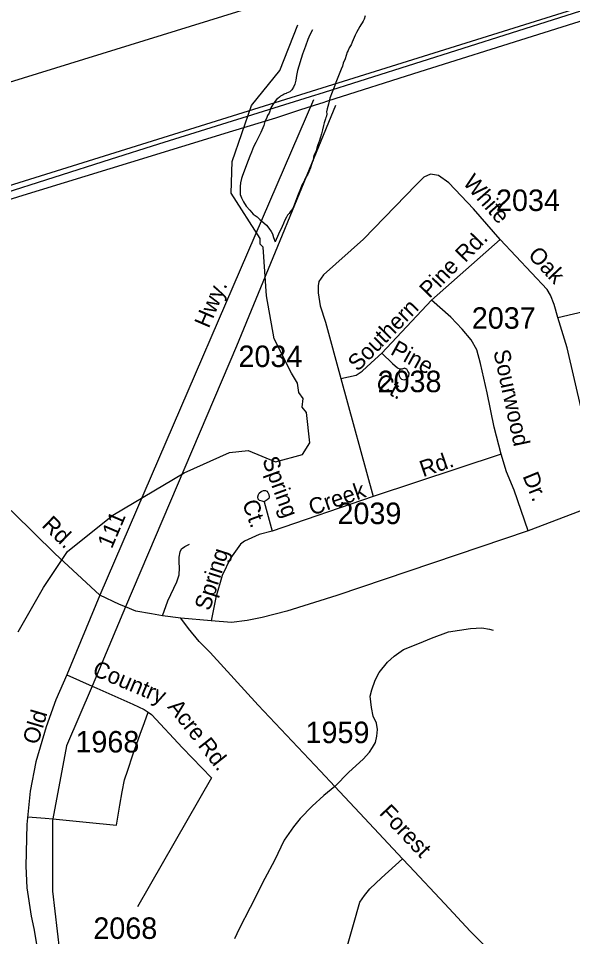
# Model space of a CAD drawing. Extents: x 2260773 to 2342389, y 552869 to 618546.
# Drawn here: x 2313503 to 2316729, y 575994 to 581334 of the extents above; entities that cross this region are included whole.
import ezdxf

# ---------------------------------------------------------------- set-up
doc = ezdxf.new("R2010")
doc.units = 0
for name, color, linetype in [('Exist Aviation Commercial or Municipal Perimeter Paved', 7, 'Continuous'), ('Exist Boundary Land Use Reservation Military US Department of Defense', 7, 'Continuous'), ('Exist Boundary Political City Limit New', 7, 'Continuous'), ('Exist Boundary Political Urban Extension UEB', 7, 'Continuous'), ('Exist Hydrographic Misc Water Feature', 7, 'Continuous'), ('Exist Road Non-System Type 51', 7, 'Continuous'), ('Exist Road Non-System Type 51 Label', 7, 'Continuous'), ('Exist Road Secondary Type 51 Attributed', 7, 'Continuous'), ('Exist Road Secondary Type 51 Label', 7, 'Continuous'), ('Exist Road Secondary Type 51 Number Label', 7, 'Continuous'), ('Map Preparation Boundary City Limit Buffer Line', 7, 'Continuous')]:
    doc.layers.add(name, color=color, linetype=linetype)

msp = doc.modelspace()

# ---------------------------------------------------------------- linework, layer by layer
at = {"layer": 'Exist Aviation Commercial or Municipal Perimeter Paved'}
msp.add_lwpolyline([(2316391.2, 581871.9), (2313259.5, 580902.9), (2308808.6, 579533.6), (2306700.6, 578883.4), (2306637, 578862.6), (2306607.1, 578850.4)], dxfattribs=at)
at = {"layer": 'Exist Boundary Land Use Reservation Military US Department of Defense'}
msp.add_line((2317609.8, 581659), (2311535.5, 579763.7), dxfattribs=at)
at = {"layer": 'Exist Boundary Political City Limit New'}
for points in [[(2317147.2, 581434.1), (2315839.8, 581022.8), (2315302, 580851.4), (2315268.5, 580840.8), (2315261.8, 580838.6), (2315139.2, 580800.2), (2315046.5, 580769.4), (2315000, 580753.9)], [(2315000, 580753.9), (2314749.5, 580677.9), (2314155.2, 580496.1), (2313504.5, 580295.5), (2313282, 580226.7)]]:
    msp.add_lwpolyline(points, dxfattribs=at)
at = {"layer": 'Exist Boundary Political Urban Extension UEB'}
msp.add_line((2314127.2, 577910.7), (2313932, 577451), dxfattribs=at)
for points in [[(2315348.4, 580828), (2314772, 579428.4), (2314127.2, 577910.7)], [(2313932, 577451), (2313784, 577102.6), (2313703.2, 576678.7)], [(2313703.2, 576678.7), (2313701.6, 576670.4), (2313701.6, 576258.8), (2313742.8, 575908.9), (2313886.9, 575517.8), (2314133.9, 575167.9), (2314689.7, 574612.2), (2315604, 573728.1)]]:
    msp.add_lwpolyline(points, dxfattribs=at)
at = {"layer": 'Exist Hydrographic Misc Water Feature'}
for points in [[(2315521.3, 581348.9), (2315515.6, 581328.7), (2315509.2, 581316.7), (2315503.7, 581308.6), (2315495.7, 581296.8), (2315489.8, 581286.7), (2315479.9, 581268.4), (2315470.1, 581252.4), (2315462.3, 581236.1), (2315450.8, 581208.2), (2315445, 581196.1), (2315438.9, 581180), (2315427.4, 581161.9), (2315421.7, 581147.7), (2315417.4, 581137.9), (2315404, 581097.7), (2315394, 581073.7), (2315388.5, 581055.4), (2315380.9, 581037.5), (2315357.5, 580979.4), (2315351.5, 580961.3), (2315347.6, 580953.3), (2315343.8, 580943), (2315329.8, 580904.9), (2315316.5, 580868.8), (2315307, 580834.9), (2315299.5, 580806.8), (2315297.2, 580790.6), (2315297.8, 580778.8), (2315296, 580764.8), (2315292.1, 580756.9), (2315289.8, 580748.7), (2315281.8, 580726.8), (2315278.3, 580710.7), (2315272.6, 580686.4), (2315266.9, 580662.5), (2315261.1, 580642.3), (2315253.3, 580618.4), (2315251.3, 580614.2), (2315245.7, 580598.4), (2315243.3, 580592.3), (2315235.7, 580564.2), (2315231.8, 580556.3), (2315227.9, 580548), (2315224, 580540), (2315220.5, 580526), (2315218.7, 580510), (2315212.5, 580495.9), (2315208.8, 580483.9), (2315206.8, 580477.7), (2315203.3, 580463.7), (2315187.5, 580427.9), (2315175.6, 580409.5)], [(2313502.2, 577765.9), (2313649.2, 578024.5), (2313789.3, 578233.6), (2314053.4, 578444.4), (2314467.4, 578690.9), (2314732.3, 578809.8), (2314840.4, 578820.8), (2314999.3, 578755), (2315157.4, 578797.5), (2315198.4, 578864.8), (2315179.3, 579041.2), (2315154.3, 579073), (2315161.3, 579122.5), (2315136.2, 579157.6), (2315127.2, 579213), (2315093.2, 579270.8), (2314991.3, 579470.1), (2314947.2, 579721), (2314927.3, 580002.4), (2314910.3, 580021.3), (2314910.3, 580054.2), (2314741.3, 580316.4), (2314747.3, 580500.5), (2314860.2, 580826.6), (2315024.3, 581030.2), (2315130.3, 581296.9)], [(2315214.2, 581267.4), (2315198.6, 581237.3), (2315187.1, 581211.5), (2315173.4, 581173), (2315155.7, 581124.9), (2315126.8, 581030.8), (2315121.3, 581000.7), (2315117.4, 580974.6), (2315111.8, 580950.7), (2315103.8, 580934.4), (2315094, 580918.5), (2315082.3, 580906.5), (2315064.3, 580898.2), (2315060.6, 580896.4), (2315054.2, 580894), (2315050.5, 580892.2), (2315044.6, 580889.8), (2315036.8, 580885.7), (2315028.4, 580881.7), (2315022.4, 580875.7), (2315012.8, 580867.4), (2315004.6, 580861.4), (2314997, 580851.5), (2314989, 580841.5), (2314983.1, 580833.4), (2314977.5, 580823.3), (2314973.2, 580813.4), (2314961.9, 580783.1), (2314953.5, 580768.9), (2314948, 580751.1), (2314938.2, 580733.1), (2314930.8, 580710.7), (2314914.6, 580670.5), (2314904.9, 580650.5), (2314895.3, 580630.5), (2314885.5, 580612.5), (2314871.7, 580586.2), (2314860.4, 580556.2), (2314850.4, 580532.2), (2314841, 580508.1), (2314808, 580419.8), (2314802, 580401.6), (2314796.3, 580377.7), (2314794.2, 580355.7), (2314793, 580327.5), (2314793, 580309.7), (2314801.2, 580289.8), (2314813.3, 580267.7), (2314829.3, 580242.2), (2314849.6, 580218.5), (2314870.3, 580194.3), (2314892.4, 580178.8), (2314908.2, 580165), (2314930.6, 580145), (2314947, 580131.2), (2314960.5, 580113.4), (2314975.1, 580093.7), (2314981.2, 580079.8), (2314987.8, 580059.8), (2314997.8, 580033.9)], [(2315175.6, 580409.5), (2315169.7, 580397.8), (2315163.5, 580383.7), (2315152.2, 580363.5), (2315144, 580343.2), (2315130.7, 580309.1), (2315121.3, 580285), (2315107.3, 580247), (2315099.5, 580228.7), (2315085.6, 580208.9), (2315079.6, 580198.8), (2315070, 580188.5), (2315064.1, 580178.5), (2315052.2, 580156.3), (2315046.6, 580140.5), (2315038.8, 580124.3), (2315017.1, 580078), (2314997.8, 580033.9)]]:
    msp.add_lwpolyline(points, dxfattribs=at)
at = {"layer": 'Exist Road Non-System Type 51'}
msp.add_line((2314037.6, 580513), (2312481.5, 580018.9), dxfattribs=at)
for points in [[(2317609.8, 581659), (2317591.1, 581637.1), (2317531.5, 581598.5), (2316933.8, 581426.6), (2315245.6, 580891.4), (2315231.8, 580887.1)], [(2315231.8, 580887.1), (2314318, 580602.1), (2314037.6, 580513)], [(2315618.1, 579387.3), (2315681.3, 579325.9), (2315709.2, 579301.8), (2315727.8, 579294.3)], [(2315727.8, 579294.3), (2315719.7, 579286.2), (2315717.8, 579278.3), (2315717.9, 579266.3), (2315718.2, 579254.3), (2315724.3, 579242.4), (2315732.3, 579236.5), (2315748.3, 579232.5), (2315760.4, 579234.8), (2315770.2, 579244.8), (2315776, 579252.9), (2315777.9, 579271), (2315769.8, 579282.8), (2315763.6, 579292.8), (2315757.7, 579294.7), (2315749.6, 579298.6), (2315735.8, 579294.5), (2315727.8, 579294.3)], [(2314933.2, 578522.2), (2314921.1, 578526.1), (2314907.1, 578529.9), (2314899, 578537.8), (2314896.8, 578551.9), (2314900.8, 578563.9), (2314904.6, 578571.9), (2314916.4, 578581.9), (2314930.4, 578588.1), (2314940.4, 578588.3), (2314948.5, 578584.4), (2314954.5, 578576.5), (2314960.7, 578564.5), (2314962.9, 578550.6), (2314960.8, 578542.5), (2314951, 578534.5), (2314945.1, 578530.3), (2314933.2, 578522.2)], [(2314933.2, 578522.2), (2314980.9, 578352.2)], [(2314341.5, 577860), (2314372.7, 577946.3), (2314425.4, 578056.9), (2314439, 578097), (2314440.5, 578138.9), (2314438.2, 578171), (2314439.8, 578200.9), (2314445.4, 578230.9), (2314453.2, 578249), (2314471.1, 578263.2), (2314499, 578275.5)], [(2315345.4, 576866.6), (2315425.4, 576950.4), (2315510.3, 577025.1), (2315545.6, 577066.6), (2315564.2, 577093.5), (2315580.8, 577122.5), (2315589.1, 577159.9), (2315593.2, 577197.2), (2315587, 577234.5), (2315568.4, 577276), (2315558, 577325.8), (2315549.7, 577392.1), (2315560.1, 577429.4), (2315578.7, 577485.4), (2315603.6, 577529), (2315651.3, 577589.1), (2315690.6, 577624.4), (2315744.5, 577663.8), (2315837.8, 577701.1), (2315908.2, 577730.1), (2316005.6, 577765.4), (2316134.1, 577786.1), (2316200.4, 577790.2), (2316243.9, 577781.9), (2316266.7, 577775.7)], [(2314075, 576641.2), (2314094.1, 576757.8), (2314106.8, 576836), (2314121.4, 576905.2), (2314139.6, 576961.7), (2314168.7, 577050.9), (2314212.4, 577171), (2314237.8, 577238.4), (2314257.5, 577299.3)], [(2315345.4, 576866.6), (2315280.1, 576813.6), (2315212.8, 576751.7), (2315143.6, 576680.7), (2315103.6, 576631.5), (2315049, 576555.1), (2314994.4, 576436.7), (2314938, 576331.1), (2314852.5, 576163.6), (2314788.8, 576039.8), (2314761.5, 575979.8)], [(2313558.3, 576690.4), (2313658.4, 576683.1), (2313703.2, 576678.7)], [(2313703.2, 576678.7), (2313896.7, 576659.4), (2314075, 576641.2)], [(2315398.3, 575874.2), (2315452.9, 576063.5), (2315491.1, 576194.6), (2315516.6, 576232.8), (2315547.5, 576271), (2315616.7, 576334.8), (2315739, 576446)]]:
    msp.add_lwpolyline(points, dxfattribs=at)
at = {"layer": 'Exist Road Secondary Type 51 Attributed'}
for p, q in [((2315220, 580859.6), (2313977, 577978.6)), ((2315908.2, 579695.9), (2316307, 580048.1)), ((2315380.2, 579240.4), (2315567.6, 578552.9)), ((2316312.3, 578800.1), (2315567.6, 578552.9)), ((2316907.1, 578520.2), (2316469.8, 578354.3)), ((2313977, 577978.6), (2313785.7, 577516.9)), ((2314624.4, 577829.6), (2314447.8, 577845.6))]:
    msp.add_line(p, q, dxfattribs=at)
for points in [[(2316307, 580048.1), (2316151.2, 580226.3), (2316007.5, 580376.7), (2315947.1, 580420.1), (2315901, 580427.4), (2315863.3, 580411.1), (2315817.8, 580366.6), (2315511.4, 580049.6), (2315278.9, 579843), (2315251, 579804), (2315247.3, 579777.9), (2315247.3, 579737), (2315260.3, 579662.6), (2315290.1, 579567.7), (2315380.2, 579240.4)], [(2313977, 577978.6), (2313716.2, 578221.6), (2313475.5, 578458), (2313305, 578615.2), (2313195.8, 578722.3), (2313126.7, 578800.3), (2313055.4, 578885), (2312947.3, 579089.1), (2312749, 579526.1), (2312579.6, 579896.3), (2312530.6, 579961), (2312481.5, 580018.9)], [(2316641.8, 579594.3), (2316621.1, 579668.9), (2316600.4, 579724.9), (2316579.8, 579757.1), (2316307, 580048.1)], [(2315380.2, 579240.4), (2315469.4, 579259), (2315502.9, 579281.3), (2315556.8, 579329.7), (2315618.1, 579387.3), (2315908.2, 579695.9)], [(2316312.3, 578800.1), (2316272.9, 578955.6), (2316230.5, 579156.8), (2316193.2, 579326.8), (2316170.4, 579405.6), (2316138.2, 579463.7), (2316086.4, 579525.9), (2316020.1, 579596.4), (2315908.2, 579695.9)], [(2316641.8, 579594.3), (2316948.6, 579665.1), (2317006.4, 579677), (2317056.2, 579677), (2317118.7, 579665), (2317305.1, 579615.1), (2317931.7, 579459.6), (2318198.4, 579374.6), (2318256.6, 579351.3), (2318283.4, 579332.6), (2318297.4, 579304.6), (2318318.4, 579253.4), (2318398.7, 579025)], [(2316781.7, 579048.9), (2316696.7, 579418), (2316641.8, 579594.3)], [(2316469.8, 578354.3), (2316389, 578590.7), (2316343.4, 578696.4), (2316312.3, 578800.1)], [(2315567.6, 578552.9), (2314980.9, 578352.2), (2314904.2, 578331.5), (2314819.2, 578294.1), (2314796.4, 578275.5), (2314738.4, 578194.6), (2314688.7, 578093), (2314651.4, 577966.5), (2314624.4, 577829.6)], [(2316469.8, 578354.3), (2315356, 577976.9), (2315065.8, 577885.6), (2314922.8, 577850.4), (2314833.7, 577831.7), (2314742.6, 577821.3), (2314624.4, 577829.6)], [(2314447.8, 577845.6), (2314341.5, 577860), (2314277.5, 577871.3), (2314187.2, 577886.4), (2314127.2, 577910.7), (2314091, 577925.3), (2313977, 577978.6)], [(2316219.5, 575938.5), (2316132.2, 576024.7), (2315984.2, 576183.7), (2315776.8, 576405.8), (2315739, 576446), (2315517.2, 576682.5), (2315345.4, 576866.6), (2315261.3, 576956.8), (2314898.6, 577339.1), (2314618.4, 577645), (2314555.3, 577710.5), (2314492.3, 577785.8), (2314447.8, 577845.6)], [(2313785.7, 577516.9), (2313721.1, 577371.3), (2313664.7, 577212.9), (2313603.8, 577010.8), (2313571, 576839.7), (2313551.9, 576644.9), (2313546.5, 576402.7), (2313552.8, 576277.1), (2313578.3, 576113.3), (2313592.9, 576040.4), (2313610.1, 575938.5), (2313639.3, 575827.4), (2313709.3, 575636.3), (2313762.1, 575512.5), (2313858.5, 575339.5), (2313900.3, 575274), (2313960.4, 575181.1), (2314069.6, 575024.6)], [(2313785.7, 577516.9), (2313932, 577451), (2313959.5, 577438.7), (2314168.4, 577346.4), (2314235.1, 577314.9), (2314257.5, 577299.3), (2314277, 577285.7), (2314458, 577090.9), (2314626.3, 576918)], [(2314626.3, 576918), (2314197.1, 576167.2)]]:
    msp.add_lwpolyline(points, dxfattribs=at)
at = {"layer": 'Map Preparation Boundary City Limit Buffer Line'}
for points in [[(2317147.2, 581434.1), (2315839.8, 581022.8), (2315302, 580851.4), (2315268.5, 580840.8), (2315261.8, 580838.6), (2315139.2, 580800.2), (2315046.5, 580769.4), (2315000, 580753.9)], [(2315000, 580753.9), (2314749.5, 580677.9), (2314155.2, 580496.1), (2313504.5, 580295.5), (2313282, 580226.7)]]:
    msp.add_lwpolyline(points, dxfattribs=at)

# ---------------------------------------------------------------- texts
at = {"layer": 'Exist Road Non-System Type 51 Label'}
for s, rotation, p in [('Pine', 330.9821, (2315662.7, 579383.1)), ('Ct.', 330.9821, (2315575, 579192.5)), ('Spring', 289.9473, (2314921, 578766.6)), ('Ct.', 289.9473, (2314804.2, 578515.8))]:
    msp.add_text(s, height=95, rotation=rotation, dxfattribs=at).set_placement(p)
at = {"layer": 'Exist Road Secondary Type 51 Label'}
for s, rotation, p in [('White', 311.1634, (2316085.8, 580375.9)), ('Rd.', 45.7664, (2316103.7, 579909)), ('Oak', 313.1509, (2316464, 579952.6)), ('Pine', 45.9888, (2315895.6, 579701.8)), ('Hwy.', 66.9032, (2314611, 579527.1)), ('Southern', 45.6176, (2315478.4, 579275.7)), ('Sourwood', 282.22, (2316266.8, 579397.5)), ('Rd.', 19.0997, (2315858.2, 578664.7)), ('Dr.', 292.0044, (2316436, 578672.4)), ('Creek', 19.0997, (2315212.2, 578441.2)), ('Rd.', 315.9798, (2313634.7, 578381)), ('111', 66.9032, (2314046.6, 578244.8)), ('Spring', 72.2614, (2314616.4, 577883.6)), ('Country', 337.1783, (2313927.6, 577515.9)), ('Acre', 308.413, (2314367.4, 577327.8)), ('Old', 73.5195, (2313616.8, 577105.5)), ('Rd.', 308.413, (2314544.6, 577104.3)), ('Forest', 313.2963, (2315598.4, 576708))]:
    msp.add_text(s, height=95, rotation=rotation, dxfattribs=at).set_placement(p)
at = {"layer": 'Exist Road Secondary Type 51 Number Label'}
for s, p in [('2034', (2316282.7, 580213.6)), ('2037', (2316141.8, 579528.9)), ('2034', (2314783.9, 579306.1)), ('2038', (2315593.4, 579159.9)), ('2039', (2315360, 578392.7)), ('1959', (2315174.3, 577118.8)), ('1968', (2313835.1, 577064.5)), ('2068', (2313939.4, 575980.4))]:
    msp.add_text(s, height=125, dxfattribs=at).set_placement(p)

doc.saveas('drawing.dxf')
